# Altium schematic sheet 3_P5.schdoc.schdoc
size 309 x 223 mm; Symbol: A4_Schematic_0605; Device: A4_Schematic_0605; @Project Name: MDIO-Board_Rev_01(0124); @Page Count: 10; @Update Date: 2024-05-21; @Create Date: 2024-05-19; @Schematic Name: Schematic1; @Page No: 5; @Page Name: P5
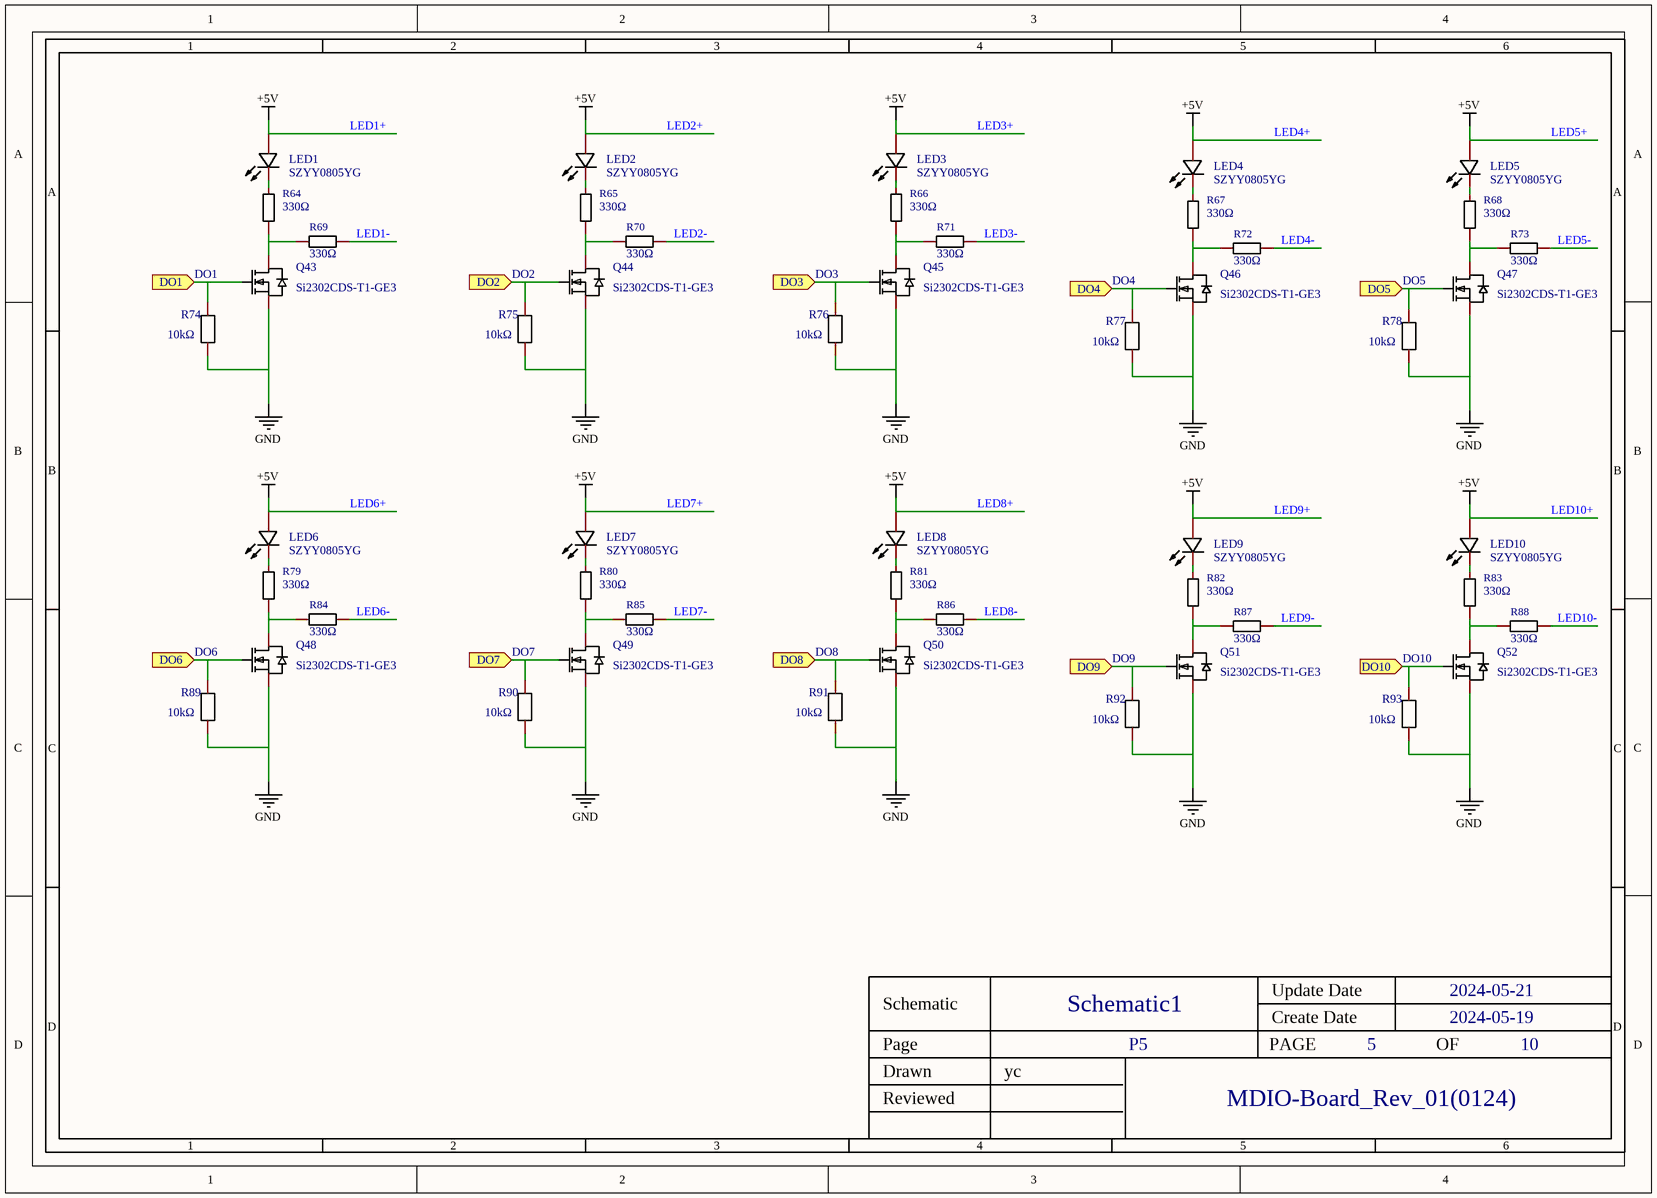
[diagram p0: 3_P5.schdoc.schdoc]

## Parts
LED1  SZYY0805YG  [LED0805-R-RD_GREEN]
LED2  SZYY0805YG  [LED0805-R-RD_GREEN]
LED3  SZYY0805YG  [LED0805-R-RD_GREEN]
LED4  SZYY0805YG  [LED0805-R-RD_GREEN]
LED5  SZYY0805YG  [LED0805-R-RD_GREEN]
LED6  SZYY0805YG  [LED0805-R-RD_GREEN]
LED7  SZYY0805YG  [LED0805-R-RD_GREEN]
LED8  SZYY0805YG  [LED0805-R-RD_GREEN]
LED9  SZYY0805YG  [LED0805-R-RD_GREEN]
LED10  SZYY0805YG  [LED0805-R-RD_GREEN]
Q43  Si2302CDS-T1-GE3  [SOT-23_L2.9-W1.3-P1.90-LS2.4-BR]
Q44  Si2302CDS-T1-GE3  [SOT-23_L2.9-W1.3-P1.90-LS2.4-BR]
Q45  Si2302CDS-T1-GE3  [SOT-23_L2.9-W1.3-P1.90-LS2.4-BR]
Q46  Si2302CDS-T1-GE3  [SOT-23_L2.9-W1.3-P1.90-LS2.4-BR]
Q47  Si2302CDS-T1-GE3  [SOT-23_L2.9-W1.3-P1.90-LS2.4-BR]
Q48  Si2302CDS-T1-GE3  [SOT-23_L2.9-W1.3-P1.90-LS2.4-BR]
Q49  Si2302CDS-T1-GE3  [SOT-23_L2.9-W1.3-P1.90-LS2.4-BR]
Q50  Si2302CDS-T1-GE3  [SOT-23_L2.9-W1.3-P1.90-LS2.4-BR]
Q51  Si2302CDS-T1-GE3  [SOT-23_L2.9-W1.3-P1.90-LS2.4-BR]
Q52  Si2302CDS-T1-GE3  [SOT-23_L2.9-W1.3-P1.90-LS2.4-BR]
R64  330Ω  [R0603]
R65  330Ω  [R0603]
R66  330Ω  [R0603]
R67  330Ω  [R0603]
R68  330Ω  [R0603]
R69  330Ω  [R0603]
R70  330Ω  [R0603]
R71  330Ω  [R0603]
R72  330Ω  [R0603]
R73  330Ω  [R0603]
R74  10kΩ  [R0603]
R75  10kΩ  [R0603]
R76  10kΩ  [R0603]
R77  10kΩ  [R0603]
R78  10kΩ  [R0603]
R79  330Ω  [R0603]
R80  330Ω  [R0603]
R81  330Ω  [R0603]
R82  330Ω  [R0603]
R83  330Ω  [R0603]
R84  330Ω  [R0603]
R85  330Ω  [R0603]
R86  330Ω  [R0603]
R87  330Ω  [R0603]
R88  330Ω  [R0603]
R89  10kΩ  [R0603]
R90  10kΩ  [R0603]
R91  10kΩ  [R0603]
R92  10kΩ  [R0603]
R93  10kΩ  [R0603]

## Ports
DO1 (in), DO2 (in), DO3 (in), DO4 (in), DO5 (in), DO6 (in), DO7 (in), DO8 (in), DO9 (in), DO10 (in)

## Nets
GND: Q43.2(S) Q44.2(S) Q45.2(S) Q46.2(S) Q47.2(S) Q48.2(S) Q49.2(S) Q50.2(S) Q51.2(S) Q52.2(S) R74.1 R75.1 R76.1 R77.1 R78.1 R89.1 R90.1 R91.1 R92.1 R93.1
LED1+: LED1.1(+) LED2.1(+) LED3.1(+) LED4.1(+) LED5.1(+) LED6.1(+) LED7.1(+) LED8.1(+) LED9.1(+) LED10.1(+)  [also labelled +5V, LED10+, LED2+, LED3+, LED4+, LED5+, LED6+, LED7+, LED8+, LED9+]
DO1: Q43.1(G) R74.2 ; port DO1
DO2: Q44.1(G) R75.2 ; port DO2
DO3: Q45.1(G) R76.2 ; port DO3
DO4: Q46.1(G) R77.2 ; port DO4
DO5: Q47.1(G) R78.2 ; port DO5
DO6: Q48.1(G) R89.2 ; port DO6
DO7: Q49.1(G) R90.2 ; port DO7
DO8: Q50.1(G) R91.2 ; port DO8
DO9: Q51.1(G) R92.2 ; port DO9
DO10: Q52.1(G) R93.2 ; port DO10
LED1-: R69.1
LED2-: R70.1
LED3-: R71.1
LED4-: R72.1
LED5-: R73.1
LED6-: R84.1
LED7-: R85.1
LED8-: R86.1
LED9-: R87.1
LED10-: R88.1
NetLED1_2: LED1.2(-) R64.2
NetLED2_2: LED2.2(-) R65.2
NetLED3_2: LED3.2(-) R66.2
NetLED4_2: LED4.2(-) R67.2
NetLED5_2: LED5.2(-) R68.2
NetLED6_2: LED6.2(-) R79.2
NetLED7_2: LED7.2(-) R80.2
NetLED8_2: LED8.2(-) R81.2
NetLED9_2: LED9.2(-) R82.2
NetLED10_2: LED10.2(-) R83.2
NetQ43_3: Q43.3(D) R64.1 R69.2
NetQ44_3: Q44.3(D) R65.1 R70.2
NetQ45_3: Q45.3(D) R66.1 R71.2
NetQ46_3: Q46.3(D) R67.1 R72.2
NetQ47_3: Q47.3(D) R68.1 R73.2
NetQ48_3: Q48.3(D) R79.1 R84.2
NetQ49_3: Q49.3(D) R80.1 R85.2
NetQ50_3: Q50.3(D) R81.1 R86.2
NetQ51_3: Q51.3(D) R82.1 R87.2
NetQ52_3: Q52.3(D) R83.1 R88.2

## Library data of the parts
LED1-LED10 = SZYY0805YG: Manufacturer: yongyu(永裕光电); Add into BOM: yes; Emitted Color: Green-yellow; Description: Emitted Color:Green-yellow
Q43-Q52 = Si2302CDS-T1-GE3: Manufacturer: VISHAY(威世); Add into BOM: yes; Type: 1个NChannel; Drain Source On Resistance (RDS(on)@Vgs,Id): 57mΩ@4.5V,3.6A; Gate Threshold Voltage (Vgs(th)@Id): 850mV@250uA; Total Gate Charge (Qg@Vgs): 5.5nC@4.5V; Description: Type:1个NChannel Drain Source Voltage (Vdss): Continuous Drain Current (Id): Power Dissipation (Pd): Drain Source On Resistance (RDS(on)@Vgs,Id):57mΩ@4.5V,3.6A Gate Threshold Voltage (Vgs(th)@Id):850mV@250uA Total Gate Charge (Qg@Vgs):5.5nC@4.5V Operating
R64-R73 R79-R88 = 0603WAF3300T5E: Manufacturer: UNI-ROYAL(厚声); Add into BOM: yes; Tolerance: ±1%; Temperature Coefficient: ±100ppm/℃; Description: Type:Thick Film Resistors Resistance: Tolerance:±1% Tolerance:±1% Power(Watts): Overload Voltage (Max): Temperature Coefficient:±100ppm/℃ Temperature Coefficient:±100ppm/℃ Operating Temperature Range:-55℃~+155℃ Operating Temperature Range:-55℃~+155℃
R74-R78 R89-R93 = SCR0603J10K: Manufacturer: VO(翔胜); Add into BOM: yes; Tolerance: ±5%; Description: Type:Thick Film Resistors Resistance: Tolerance:±5% Tolerance:±5% Power(Watts): Overload Voltage (Max): Operating Temperature Range:-55℃~+155℃ Operating Temperature Range:-55℃~+155℃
